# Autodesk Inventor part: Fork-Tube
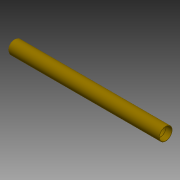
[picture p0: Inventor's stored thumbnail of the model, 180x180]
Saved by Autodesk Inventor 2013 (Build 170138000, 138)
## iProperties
Shininess: 64.0
Length Units: 11272
Angle Units: 11279
Time Units: 11290
Mass Units: 11286
Length Display Precision: 3
Angle Display Precision: 2
Compacted: True
Created: 2001-11
Part Number: Fork-Tube
Document SubType Name: Modeling
Designer: Autodesk, Inc.
Mass: 63.0746 g
Surface Area: 510.582 cm^2
Volume: 63.0746 cm^3
Density: 1 g/cm^3
Material: Generic
Density: 0.0
Volumn: 0.0
Area: 0.0
PropertySet Name: Model Information
Control State: 0
Master: False
Checked Out: False
Author: Autodesk, Inc.
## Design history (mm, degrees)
sketch "Sketch1"
  geometry: L1 (361.822, 239.265)-(361.822, 240.154); L2 (361.822, 240.154)-(364.362, 241.805); L3 (364.362, 241.805)-(679.322, 241.805); L4 (679.322, 240.535)-(679.322, 241.805); L5 (667.892, 240.535)-(679.322, 240.535); L6 (667.892, 239.265)-(667.892, 240.535); L7 (361.822, 239.265)-(667.892, 239.265); L8 (345.987, 227.835)-(749.871, 227.835); L9 (345.987, 227.835)-(749.871, 227.835)
  constraints: 18 end point, 4 horizontal, 3 vertical, 1 other
revolve "RevolutionFull1" sketch "Sketch1" stored, may be unused: angle "d0" = 360 deg
body "Solid1"
